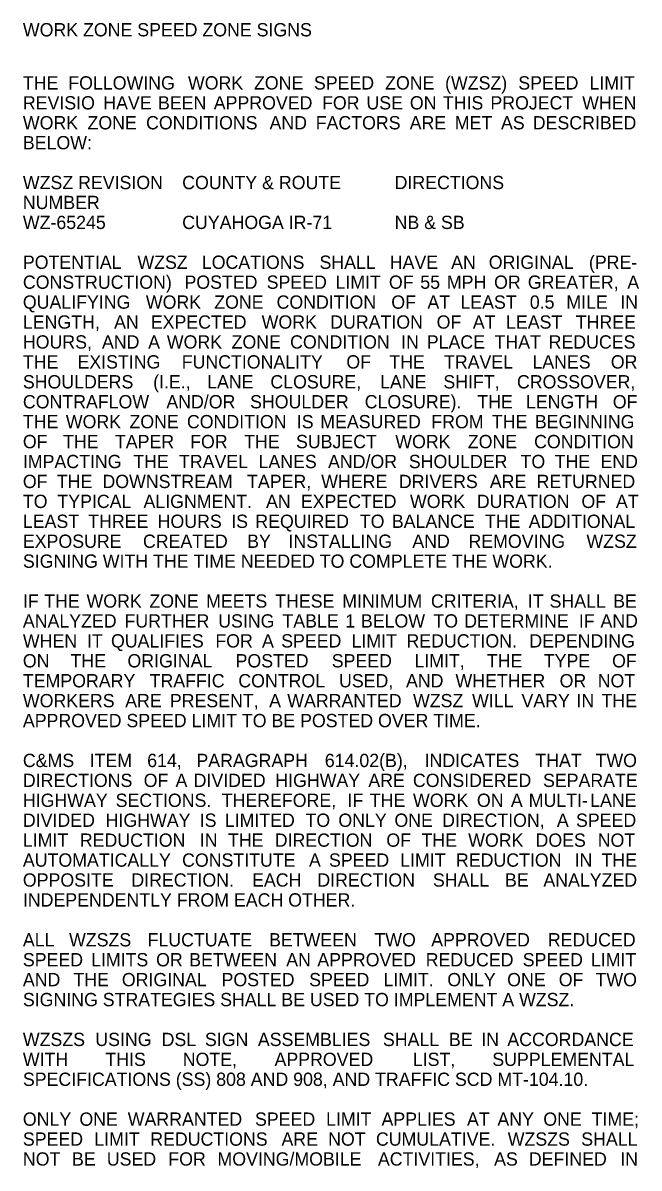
# Model space of a CAD drawing. Extents: x 0 to 43.6, y -18 to 22.
# Drawn here: x 37.09 to 43.59, y 9.07 to 21.14 of the extents above; entities that cross this region are included whole.
import ezdxf

# ---------------------------------------------------------------- set-up
doc = ezdxf.new("R2010")
doc.units = 0
doc.layers.add('SH_Text', color=7, linetype='Continuous')

msp = doc.modelspace()

# ---------------------------------------------------------------- texts
at = {"layer": 'SH_Text'}
for s, p in [('WORK ZONE SPEED ZONE SIGNS', (37.091, 21)), ('THE ', (37.091, 20.44)), ('FOLLOWING ', (37.57, 20.44)), ('WORK ', (38.832, 20.44)), ('ZONE ', (39.528, 20.44)), ('SPEED ', (40.16, 20.44)), ('ZONE ', (40.911, 20.44)), ('(WZSZ) ', (41.543, 20.44)), ('SPEED ', (42.315, 20.44)), ('LIMIT ', (43.066, 20.44)), ('REVISIO ', (37.091, 20.23)), ('HAVE ', (37.939, 20.23)), ('BEEN ', (38.516, 20.23)), ('APPROVED ', (39.104, 20.23)), ('FOR ', (40.246, 20.23)), ('USE ', (40.714, 20.23)), ('ON ', (41.172, 20.23)), ('THIS ', (41.52, 20.23)), ('PROJECT ', (42.021, 20.23)), ('WHEN ', (42.989, 20.23)), ('WORK ', (37.091, 20.02)), ('ZONE ', (37.773, 20.02)), ('CONDITIONS ', (38.39, 20.02)), ('AND ', (39.692, 20.02)), ('FACTORS ', (40.179, 20.02)), ('ARE ', (41.17, 20.02)), ('MET ', (41.646, 20.02)), ('AS ', (42.133, 20.02)), ('DESCRIBED ', (42.468, 20.02)), ('BELOW:', (37.091, 19.81)), ('WZSZ REVISION', (37.091, 19.39)), ('COUNTY & ROUTE', (38.771, 19.39)), ('DIRECTIONS', (41.011, 19.39)), ('NUMBER', (37.091, 19.18)), ('WZ-65245', (37.091, 18.97)), ('CUYAHOGA IR-71', (38.771, 18.97)), ('NB & SB', (41.011, 18.97)), ('POTENTIAL ', (37.091, 18.55)), ('WZSZ ', (38.299, 18.55)), ('LOCATIONS ', (38.978, 18.55)), ('SHALL ', (40.219, 18.55)), ('HAVE ', (40.96, 18.55)), ('AN ', (41.607, 18.55)), ('ORIGINAL ', (42.004, 18.55)), ('(PRE-', (43.06, 18.55)), ('CONSTRUCTION) ', (37.091, 18.34)), ('POSTED ', (38.795, 18.34)), ('SPEED ', (39.662, 18.34)), ('LIMIT ', (40.388, 18.34)), ('OF ', (40.951, 18.34)), ('55 ', (41.282, 18.34)), ('MPH ', (41.562, 18.34)), ('OR ', (42.06, 18.34)), ('GREATER, ', (42.416, 18.34)), ('A ', (43.465, 18.34)), ('QUALIFYING ', (37.091, 18.13)), ('WORK ', (38.388, 18.13)), ('ZONE ', (39.109, 18.13)), ('CONDITION ', (39.766, 18.13)), ('OF ', (40.976, 18.13)), ('AT ', (41.357, 18.13)), ('LEAST ', (41.705, 18.13)), ('0.5 ', (42.437, 18.13)), ('MILE ', (42.822, 18.13)), ('IN ', (43.391, 18.13)), ('LENGTH, ', (37.091, 17.92)), ('AN ', (38.053, 17.92)), ('EXPECTED ', (38.44, 17.92)), ('WORK ', (39.609, 17.92)), ('DURATION ', (40.332, 17.92)), ('OF ', (41.454, 17.92)), ('AT ', (41.836, 17.92)), ('LEAST ', (42.186, 17.92)), ('THREE ', (42.921, 17.92)), ('HOURS, ', (37.091, 17.71)), ('AND ', (37.925, 17.71)), ('A ', (38.412, 17.71)), ('WORK ', (38.609, 17.71)), ('ZONE ', (39.292, 17.71)), ('CONDITION ', (39.909, 17.71)), ('IN ', (41.08, 17.71)), ('PLACE ', (41.35, 17.71)), ('THAT ', (42.065, 17.71)), ('REDUCES ', (42.635, 17.71)), ('THE ', (37.091, 17.5)), ('EXISTING ', (37.667, 17.5)), ('FUNCTIONALITY ', (38.766, 17.5)), ('OF ', (40.502, 17.5)), ('THE ', (40.955, 17.5)), ('TRAVEL ', (41.532, 17.5)), ('LANES ', (42.464, 17.5)), ('OR ', (43.291, 17.5)), ('SHOULDERS ', (37.091, 17.29)), ('(I.E., ', (38.465, 17.29)), ('LANE ', (39.034, 17.29)), ('CLOSURE, ', (39.701, 17.29)), ('LANE ', (40.858, 17.29)), ('SHIFT, ', (41.525, 17.29)), ('CROSSOVER, ', (42.301, 17.29)), ('CONTRAFLOW ', (37.091, 17.08)), ('AND/OR ', (38.604, 17.08)), ('SHOULDER ', (39.487, 17.08)), ('CLOSURE). ', (40.696, 17.08)), ('THE ', (41.883, 17.08)), ('LENGTH ', (42.396, 17.08)), ('OF ', (43.312, 17.08)), ('THE ', (37.091, 16.87)), ('WORK ', (37.544, 16.87)), ('ZONE ', (38.215, 16.87)), ('CONDITION ', (38.821, 16.87)), ('IS ', (39.98, 16.87)), ('MEASURED ', (40.227, 16.87)), ('FROM ', (41.398, 16.87)), ('THE ', (42.037, 16.87)), ('BEGINNING ', (42.49, 16.87)), ('OF ', (37.091, 16.66)), ('THE ', (37.515, 16.66)), ('TAPER ', (38.062, 16.66)), ('FOR ', (38.855, 16.66)), ('THE ', (39.424, 16.66)), ('SUBJECT ', (39.971, 16.66)), ('WORK ', (41.018, 16.66)), ('ZONE ', (41.783, 16.66)), ('CONDITION ', (42.482, 16.66)), ('IMPACTING ', (37.091, 16.45)), ('THE ', (38.255, 16.45)), ('TRAVEL ', (38.737, 16.45)), ('LANES ', (39.576, 16.45)), ('AND/OR ', (40.309, 16.45)), ('SHOULDER ', (41.161, 16.45)), ('TO ', (42.339, 16.45)), ('THE ', (42.699, 16.45)), ('END ', (43.182, 16.45)), ('OF ', (37.091, 16.24)), ('THE ', (37.449, 16.24)), ('DOWNSTREAM ', (37.93, 16.24)), ('TAPER, ', (39.455, 16.24)), ('WHERE ', (40.237, 16.24)), ('DRIVERS ', (41.056, 16.24)), ('ARE ', (42.015, 16.24)), ('RETURNED ', (42.508, 16.24)), ('TO ', (37.091, 16.03)), ('TYPICAL ', (37.455, 16.03)), ('ALIGNMENT. ', (38.363, 16.03)), ('EXPECTED ', (40.022, 16.03)), ('WORK ', (41.173, 16.03)), ('DURATION ', (41.878, 16.03)), ('OF ', (42.981, 16.03)), ('AN ', (39.655, 16.03)), ('AT ', (43.345, 16.03)), ('LEAST ', (37.091, 15.82)), ('THREE ', (37.78, 15.82)), ('HOURS ', (38.512, 15.82)), ('IS ', (39.288, 15.82)), ('REQUIRED ', (39.542, 15.82)), ('TO ', (40.644, 15.82)), ('BALANCE ', (40.982, 15.82)), ('THE ', (41.964, 15.82)), ('ADDITIONAL ', (42.425, 15.82)), ('EXPOSURE ', (37.091, 15.61)), ('CREATED ', (38.357, 15.61)), ('BY ', (39.456, 15.61)), ('INSTALLING ', (39.892, 15.61)), ('AND ', (41.198, 15.61)), ('REMOVING ', (41.79, 15.61)), ('WZSZ ', (43.034, 15.61)), ('SIGNING WITH THE TIME NEEDED TO COMPLETE THE WORK.', (37.091, 15.4)), ('IF ', (37.091, 14.98)), ('THE ', (37.316, 14.98)), ('WORK ', (37.762, 14.98)), ('ZONE ', (38.425, 14.98)), ('MEETS ', (39.023, 14.98)), ('THESE ', (39.752, 14.98)), ('MINIMUM ', (40.459, 14.98)), ('CRITERIA, ', (41.394, 14.98)), ('IT ', (42.416, 14.98)), ('SHALL ', (42.645, 14.98)), ('BE ', (43.316, 14.98)), ('ANALYZED ', (37.091, 14.77)), ('FURTHER ', (38.163, 14.77)), ('USING ', (39.151, 14.77)), ('TABLE ', (39.828, 14.77)), ('1 ', (40.49, 14.77)), ('BELOW ', (40.656, 14.77)), ('TO ', (41.42, 14.77)), ('DETERMINE ', (41.745, 14.77)), ('IF ', (42.954, 14.77)), ('AND ', (43.182, 14.77)), ('WHEN ', (37.091, 14.56)), ('IT ', (37.767, 14.56)), ('QUALIFIES ', (38.02, 14.56)), ('FOR ', (39.121, 14.56)), ('A ', (39.613, 14.56)), ('SPEED ', (39.815, 14.56)), ('LIMIT ', (40.557, 14.56)), ('REDUCTION. ', (41.136, 14.56)), ('DEPENDING ', (42.432, 14.56)), ('ON ', (37.091, 14.35)), ('THE ', (37.593, 14.35)), ('ORIGINAL ', (38.194, 14.35)), ('POSTED ', (39.334, 14.35)), ('SPEED ', (40.348, 14.35)), ('LIMIT, ', (41.22, 14.35)), ('THE ', (41.984, 14.35)), ('TYPE ', (42.584, 14.35)), ('OF ', (43.304, 14.35)), ('TEMPORARY ', (37.091, 14.14)), ('TRAFFIC ', (38.428, 14.14)), ('CONTROL ', (39.363, 14.14)), ('USED, ', (40.425, 14.14)), ('AND ', (41.131, 14.14)), ('WHETHER ', (41.653, 14.14)), ('OR ', (42.751, 14.14)), ('NOT ', (43.153, 14.14)), ('WORKERS ', (37.091, 13.93)), ('ARE ', (38.17, 13.93)), ('PRESENT, ', (38.641, 13.93)), ('A ', (39.688, 13.93)), ('WARRANTED ', (39.879, 13.93)), ('WZSZ ', (41.205, 13.93)), ('WILL ', (41.828, 13.93)), ('VARY ', (42.349, 13.93)), ('IN ', (42.929, 13.93)), ('THE ', (43.193, 13.93)), ('APPROVED SPEED LIMIT TO BE POSTED OVER TIME.', (37.091, 13.72)), ('C&MS ', (37.091, 13.3)), ('ITEM ', (37.795, 13.3)), ('614, ', (38.402, 13.3)), ('PARAGRAPH ', (38.921, 13.3)), ('614.02(B), ', (40.275, 13.3)), ('INDICATES ', (41.327, 13.3)), ('THAT ', (42.495, 13.3)), ('TWO ', (43.13, 13.3)), ('DIRECTIONS ', (37.091, 13.09)), ('OF ', (38.365, 13.09)), ('A ', (38.701, 13.09)), ('DIVIDED ', (38.892, 13.09)), ('HIGHWAY ', (39.753, 13.09)), ('ARE ', (40.734, 13.09)), ('CONSIDERED ', (41.204, 13.09)), ('SEPARATE ', (42.576, 13.09)), ('HIGHWAY ', (37.091, 12.88)), ('SECTIONS. ', (38.069, 12.88)), ('THEREFORE, ', (39.188, 12.88)), ('IF ', (40.514, 12.88)), ('THE ', (40.749, 12.88)), ('WORK ', (41.205, 12.88)), ('ON ', (41.879, 12.88)), ('A ', (42.237, 12.88)), ('MULTI-', (42.425, 12.88)), ('LANE ', (43.073, 12.88)), ('DIVIDED ', (37.091, 12.67)), ('HIGHWAY ', (37.964, 12.67)), ('IS ', (38.956, 12.67)), ('LIMITED ', (39.22, 12.67)), ('TO ', (40.071, 12.67)), ('ONLY ', (40.418, 12.67)), ('ONE ', (41.009, 12.67)), ('DIRECTION, ', (41.512, 12.67)), ('A ', (42.722, 12.67)), ('SPEED ', (42.924, 12.67)), ('LIMIT ', (37.091, 12.46)), ('REDUCTION ', (37.692, 12.46)), ('IN ', (38.957, 12.46)), ('THE ', (39.254, 12.46)), ('DIRECTION ', (39.747, 12.46)), ('OF ', (40.924, 12.46)), ('THE ', (41.294, 12.46)), ('WORK ', (41.787, 12.46)), ('DOES ', (42.497, 12.46)), ('NOT ', (43.153, 12.46)), ('AUTOMATICALLY ', (37.091, 12.25)), ('CONSTITUTE ', (38.77, 12.25)), ('A ', (40.108, 12.25)), ('SPEED ', (40.319, 12.25)), ('LIMIT ', (41.07, 12.25)), ('REDUCTION ', (41.658, 12.25)), ('IN ', (42.909, 12.25)), ('THE ', (43.193, 12.25)), ('OPPOSITE ', (37.091, 12.04)), ('DIRECTION. ', (38.235, 12.04)), ('EACH ', (39.508, 12.04)), ('DIRECTION ', (40.196, 12.04)), ('SHALL ', (41.415, 12.04)), ('BE ', (42.175, 12.04)), ('ANALYZED ', (42.58, 12.04)), ('INDEPENDENTLY FROM EACH OTHER.', (37.091, 11.83)), ('ALL ', (37.091, 11.41)), ('WZSZS ', (37.578, 11.41)), ('FLUCTUATE ', (38.406, 11.41)), ('BETWEEN ', (39.687, 11.41)), ('TWO ', (40.798, 11.41)), ('APPROVED ', (41.397, 11.41)), ('REDUCED ', (42.627, 11.41)), ('SPEED ', (37.091, 11.2)), ('LIMITS ', (37.81, 11.2)), ('OR ', (38.496, 11.2)), ('BETWEEN ', (38.845, 11.2)), ('AN ', (39.868, 11.2)), ('APPROVED ', (40.196, 11.2)), ('REDUCED ', (41.339, 11.2)), ('SPEED ', (42.362, 11.2)), ('LIMIT ', (43.081, 11.2)), ('AND ', (37.091, 10.99)), ('THE ', (37.624, 10.99)), ('ORIGINAL ', (38.135, 10.99)), ('POSTED ', (39.186, 10.99)), ('SPEED ', (40.11, 10.99)), ('LIMIT. ', (40.893, 10.99)), ('ONLY ', (41.567, 10.99)), ('ONE ', (42.198, 10.99)), ('OF ', (42.742, 10.99)), ('TWO ', (43.13, 10.99)), ('SIGNING STRATEGIES SHALL BE USED TO IMPLEMENT A WZSZ.', (37.091, 10.78)), ('WZSZS ', (37.091, 10.36)), ('USING ', (37.855, 10.36)), ('DSL ', (38.554, 10.36)), ('SIGN ', (39.011, 10.36)), ('ASSEMBLIES ', (39.569, 10.36)), ('SHALL ', (40.888, 10.36)), ('BE ', (41.584, 10.36)), ('IN ', (41.925, 10.36)), ('ACCORDANCE ', (42.2, 10.36)), ('WITH ', (37.091, 10.15)), ('THIS ', (37.961, 10.15)), ('NOTE, ', (38.777, 10.15)), ('APPROVED ', (39.745, 10.15)), ('LIST, ', (41.203, 10.15)), ('SUPPLEMENTAL ', (42.041, 10.15)), ('SPECIFICATIONS (SS) 808 AND 908, AND TRAFFIC SCD MT-104.10.', (37.091, 9.94)), ('ONLY ', (37.091, 9.52)), ('ONE ', (37.687, 9.52)), ('WARRANTED ', (38.197, 9.52)), ('SPEED ', (39.539, 9.52)), ('LIMIT ', (40.288, 9.52)), ('APPLIES ', (40.873, 9.52)), ('AT ', (41.774, 9.52)), ('ANY ', (42.095, 9.52)), ('ONE ', (42.579, 9.52)), ('TIME; ', (43.089, 9.52)), ('SPEED ', (37.091, 9.31)), ('LIMIT ', (37.844, 9.31)), ('REDUCTIONS ', (38.434, 9.31)), ('ARE ', (39.818, 9.31)), ('NOT ', (40.31, 9.31)), ('CUMULATIVE. ', (40.814, 9.31)), ('WZSZS ', (42.204, 9.31)), ('SHALL ', (42.979, 9.31)), ('NOT ', (37.091, 9.1)), ('BE ', (37.609, 9.1)), ('USED ', (37.976, 9.1)), ('FOR ', (38.625, 9.1)), ('MOVING/MOBILE ', (39.143, 9.1)), ('ACTIVITIES, ', (40.835, 9.1)), ('AS ', (42.06, 9.1)), ('DEFINED ', (42.427, 9.1)), ('IN ', (43.391, 9.1))]:
    msp.add_text(s, height=0.14, dxfattribs=at).set_placement(p)

doc.saveas('drawing.dxf')
